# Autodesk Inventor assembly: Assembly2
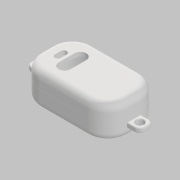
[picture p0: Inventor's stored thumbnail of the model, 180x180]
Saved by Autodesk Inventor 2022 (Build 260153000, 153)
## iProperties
Created: 2022-06
Part Number: Assembly2
Document SubType Name: Assembly
Designer: Dragon
Author: Dragon
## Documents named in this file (3)
- E:\refi\KULIAH\Semester 4\Inventor nanda\Assembly2.iam
- E:\refi\KULIAH\Semester 4\Inventor nanda\atas.ipt
- E:\refi\KULIAH\Semester 4\Inventor nanda\bawah.ipt
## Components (2 placed, 2 different names)
1. atas:1 — Mate:1, Mate:2, Mate:3
2. bawah:1 — Mate:1, Mate:2, Mate:3
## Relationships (3: Mate 3)
- Mate:1: atas:1 ↔ bawah:1
- Mate:2: atas:1 ↔ bawah:1
- Mate:3: atas:1 ↔ bawah:1
